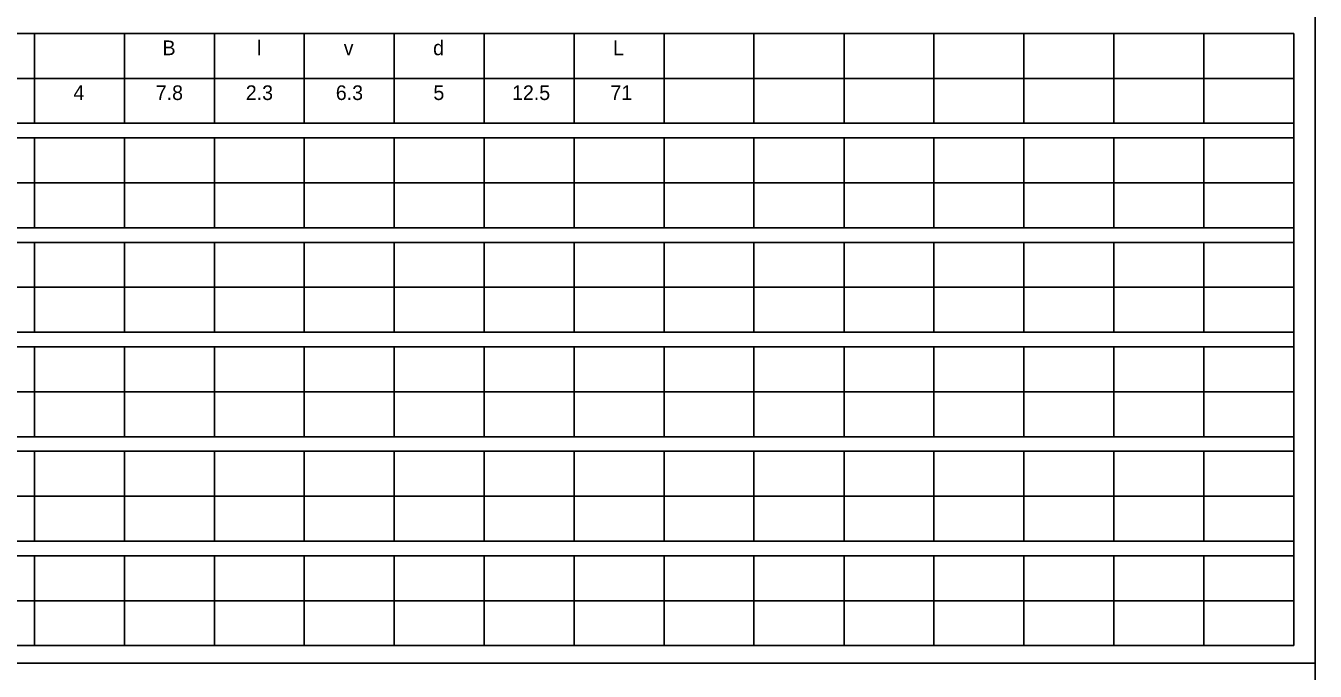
# Model space of a CAD drawing. Extents: x -998.8 to -961.2, y -2311.8 to -2287.8.
# Drawn here: x -972 to -961.22, y -2299.62 to -2294.22 of the extents above; entities that cross this region are included whole.
import ezdxf

# ---------------------------------------------------------------- set-up
doc = ezdxf.new("R2010")
doc.units = 0
doc.layers.add('GSSign', color=7, linetype='Continuous')
doc.layers.add('SheetLinesMisc2_dp', color=7, linetype='Continuous')

msp = doc.modelspace()

# ---------------------------------------------------------------- linework, layer by layer
at = {"layer": 'SheetLinesMisc2_dp'}
for p, q in [((-961.216, -2311.261), (-961.216, -2287.849)), ((-979.893, -2294.286), (-961.396, -2294.286)), ((-971.93, -2294.286), (-971.93, -2295.038)), ((-971.178, -2294.286), (-971.178, -2295.038)), ((-970.425, -2294.286), (-970.425, -2295.038)), ((-969.673, -2294.286), (-969.673, -2295.038)), ((-968.921, -2294.286), (-968.921, -2295.038)), ((-968.168, -2294.286), (-968.168, -2295.038)), ((-967.416, -2294.286), (-967.416, -2295.038)), ((-966.663, -2294.286), (-966.663, -2295.038)), ((-965.911, -2294.286), (-965.911, -2295.038)), ((-965.158, -2294.286), (-965.158, -2295.038)), ((-964.406, -2294.286), (-964.406, -2295.038)), ((-963.653, -2294.286), (-963.653, -2295.038)), ((-962.901, -2294.286), (-962.901, -2295.038)), ((-962.149, -2294.286), (-962.149, -2295.038)), ((-961.396, -2299.407), (-961.396, -2294.286)), ((-979.893, -2294.662), (-961.396, -2294.662)), ((-979.893, -2295.038), (-961.396, -2295.038)), ((-979.893, -2295.16), (-961.396, -2295.16)), ((-971.93, -2295.16), (-971.93, -2295.912)), ((-971.178, -2295.16), (-971.178, -2295.912)), ((-970.425, -2295.16), (-970.425, -2295.912)), ((-969.673, -2295.16), (-969.673, -2295.912)), ((-968.921, -2295.16), (-968.921, -2295.912)), ((-968.168, -2295.16), (-968.168, -2295.912)), ((-967.416, -2295.16), (-967.416, -2295.912)), ((-966.663, -2295.16), (-966.663, -2295.912)), ((-965.911, -2295.16), (-965.911, -2295.912)), ((-965.158, -2295.16), (-965.158, -2295.912)), ((-964.406, -2295.16), (-964.406, -2295.912)), ((-963.653, -2295.16), (-963.653, -2295.912)), ((-962.901, -2295.16), (-962.901, -2295.912)), ((-962.149, -2295.16), (-962.149, -2295.912)), ((-979.893, -2295.536), (-961.396, -2295.536)), ((-979.893, -2295.912), (-961.396, -2295.912)), ((-979.893, -2296.034), (-961.396, -2296.034)), ((-971.93, -2296.034), (-971.93, -2296.785)), ((-971.178, -2296.034), (-971.178, -2296.785)), ((-970.425, -2296.034), (-970.425, -2296.785)), ((-969.673, -2296.034), (-969.673, -2296.785)), ((-968.921, -2296.034), (-968.921, -2296.785)), ((-968.168, -2296.034), (-968.168, -2296.785)), ((-967.416, -2296.034), (-967.416, -2296.785)), ((-966.663, -2296.034), (-966.663, -2296.785)), ((-965.911, -2296.034), (-965.911, -2296.785)), ((-965.158, -2296.034), (-965.158, -2296.785)), ((-964.406, -2296.034), (-964.406, -2296.785)), ((-963.653, -2296.034), (-963.653, -2296.785)), ((-962.901, -2296.034), (-962.901, -2296.785)), ((-962.149, -2296.034), (-962.149, -2296.785)), ((-979.893, -2296.41), (-961.396, -2296.41)), ((-979.893, -2296.785), (-961.396, -2296.785)), ((-979.893, -2296.908), (-961.396, -2296.908)), ((-971.93, -2296.908), (-971.93, -2297.66)), ((-971.178, -2296.908), (-971.178, -2297.66)), ((-970.425, -2296.908), (-970.425, -2297.66)), ((-969.673, -2296.908), (-969.673, -2297.66)), ((-968.921, -2296.908), (-968.921, -2297.66)), ((-968.168, -2296.908), (-968.168, -2297.66)), ((-967.416, -2296.908), (-967.416, -2297.66)), ((-966.663, -2296.908), (-966.663, -2297.66)), ((-965.911, -2296.908), (-965.911, -2297.66)), ((-965.158, -2296.908), (-965.158, -2297.66)), ((-964.406, -2296.908), (-964.406, -2297.66)), ((-963.653, -2296.908), (-963.653, -2297.66)), ((-962.901, -2296.908), (-962.901, -2297.66)), ((-962.149, -2296.908), (-962.149, -2297.66)), ((-979.893, -2297.284), (-961.396, -2297.284)), ((-979.893, -2297.66), (-961.396, -2297.66)), ((-979.893, -2297.782), (-961.396, -2297.782)), ((-971.93, -2297.782), (-971.93, -2298.534)), ((-971.178, -2297.782), (-971.178, -2298.534)), ((-970.425, -2297.782), (-970.425, -2298.534)), ((-969.673, -2297.782), (-969.673, -2298.534)), ((-968.921, -2297.782), (-968.921, -2298.534)), ((-968.168, -2297.782), (-968.168, -2298.534)), ((-967.416, -2297.782), (-967.416, -2298.534)), ((-966.663, -2297.782), (-966.663, -2298.534)), ((-965.911, -2297.782), (-965.911, -2298.534)), ((-965.158, -2297.782), (-965.158, -2298.534)), ((-964.406, -2297.782), (-964.406, -2298.534)), ((-963.653, -2297.782), (-963.653, -2298.534)), ((-962.901, -2297.782), (-962.901, -2298.534)), ((-962.149, -2297.782), (-962.149, -2298.534)), ((-979.893, -2298.158), (-961.396, -2298.158)), ((-979.893, -2298.534), (-961.396, -2298.534)), ((-979.893, -2298.656), (-961.396, -2298.656)), ((-971.93, -2298.656), (-971.93, -2299.407)), ((-971.178, -2298.656), (-971.178, -2299.407)), ((-970.425, -2298.656), (-970.425, -2299.407)), ((-969.673, -2298.656), (-969.673, -2299.407)), ((-968.921, -2298.656), (-968.921, -2299.407)), ((-968.168, -2298.656), (-968.168, -2299.407)), ((-967.416, -2298.656), (-967.416, -2299.407)), ((-966.663, -2298.656), (-966.663, -2299.407)), ((-965.911, -2298.656), (-965.911, -2299.407)), ((-965.158, -2298.656), (-965.158, -2299.407)), ((-964.406, -2298.656), (-964.406, -2299.407)), ((-963.653, -2298.656), (-963.653, -2299.407)), ((-962.901, -2298.656), (-962.901, -2299.407)), ((-962.149, -2298.656), (-962.149, -2299.407)), ((-979.893, -2299.032), (-961.396, -2299.032)), ((-979.893, -2299.407), (-961.396, -2299.407)), ((-998.826, -2299.555), (-961.216, -2299.555))]:
    msp.add_line(p, q, dxfattribs=at)

# ---------------------------------------------------------------- texts
at = {"layer": 'GSSign'}
for s, height, p in [('B', 0.123, (-970.859, -2294.468)), ('l', 0.123, (-970.069, -2294.468)), ('v', 0.123, (-969.343, -2294.468)), ('d', 0.123, (-968.595, -2294.468)), ('L', 0.123, (-967.09, -2294.468)), ('4', 0.123, (-971.604, -2294.843)), ('7.8', 0.1225, (-970.915, -2294.843)), ('2.3', 0.1225, (-970.162, -2294.843)), ('6.3', 0.1225, (-969.409, -2294.843)), ('5', 0.123, (-968.593, -2294.843)), ('12.5', 0.1225, (-967.935, -2294.843)), ('71', 0.1225, (-967.112, -2294.843))]:
    msp.add_text(s, height=height, dxfattribs=at).set_placement(p)

doc.saveas('drawing.dxf')
